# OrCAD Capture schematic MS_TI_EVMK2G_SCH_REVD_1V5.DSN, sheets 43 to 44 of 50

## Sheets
43 42. JTAG_XDS200_CPLD: size C; title: JTAG_XDS200_CPLD
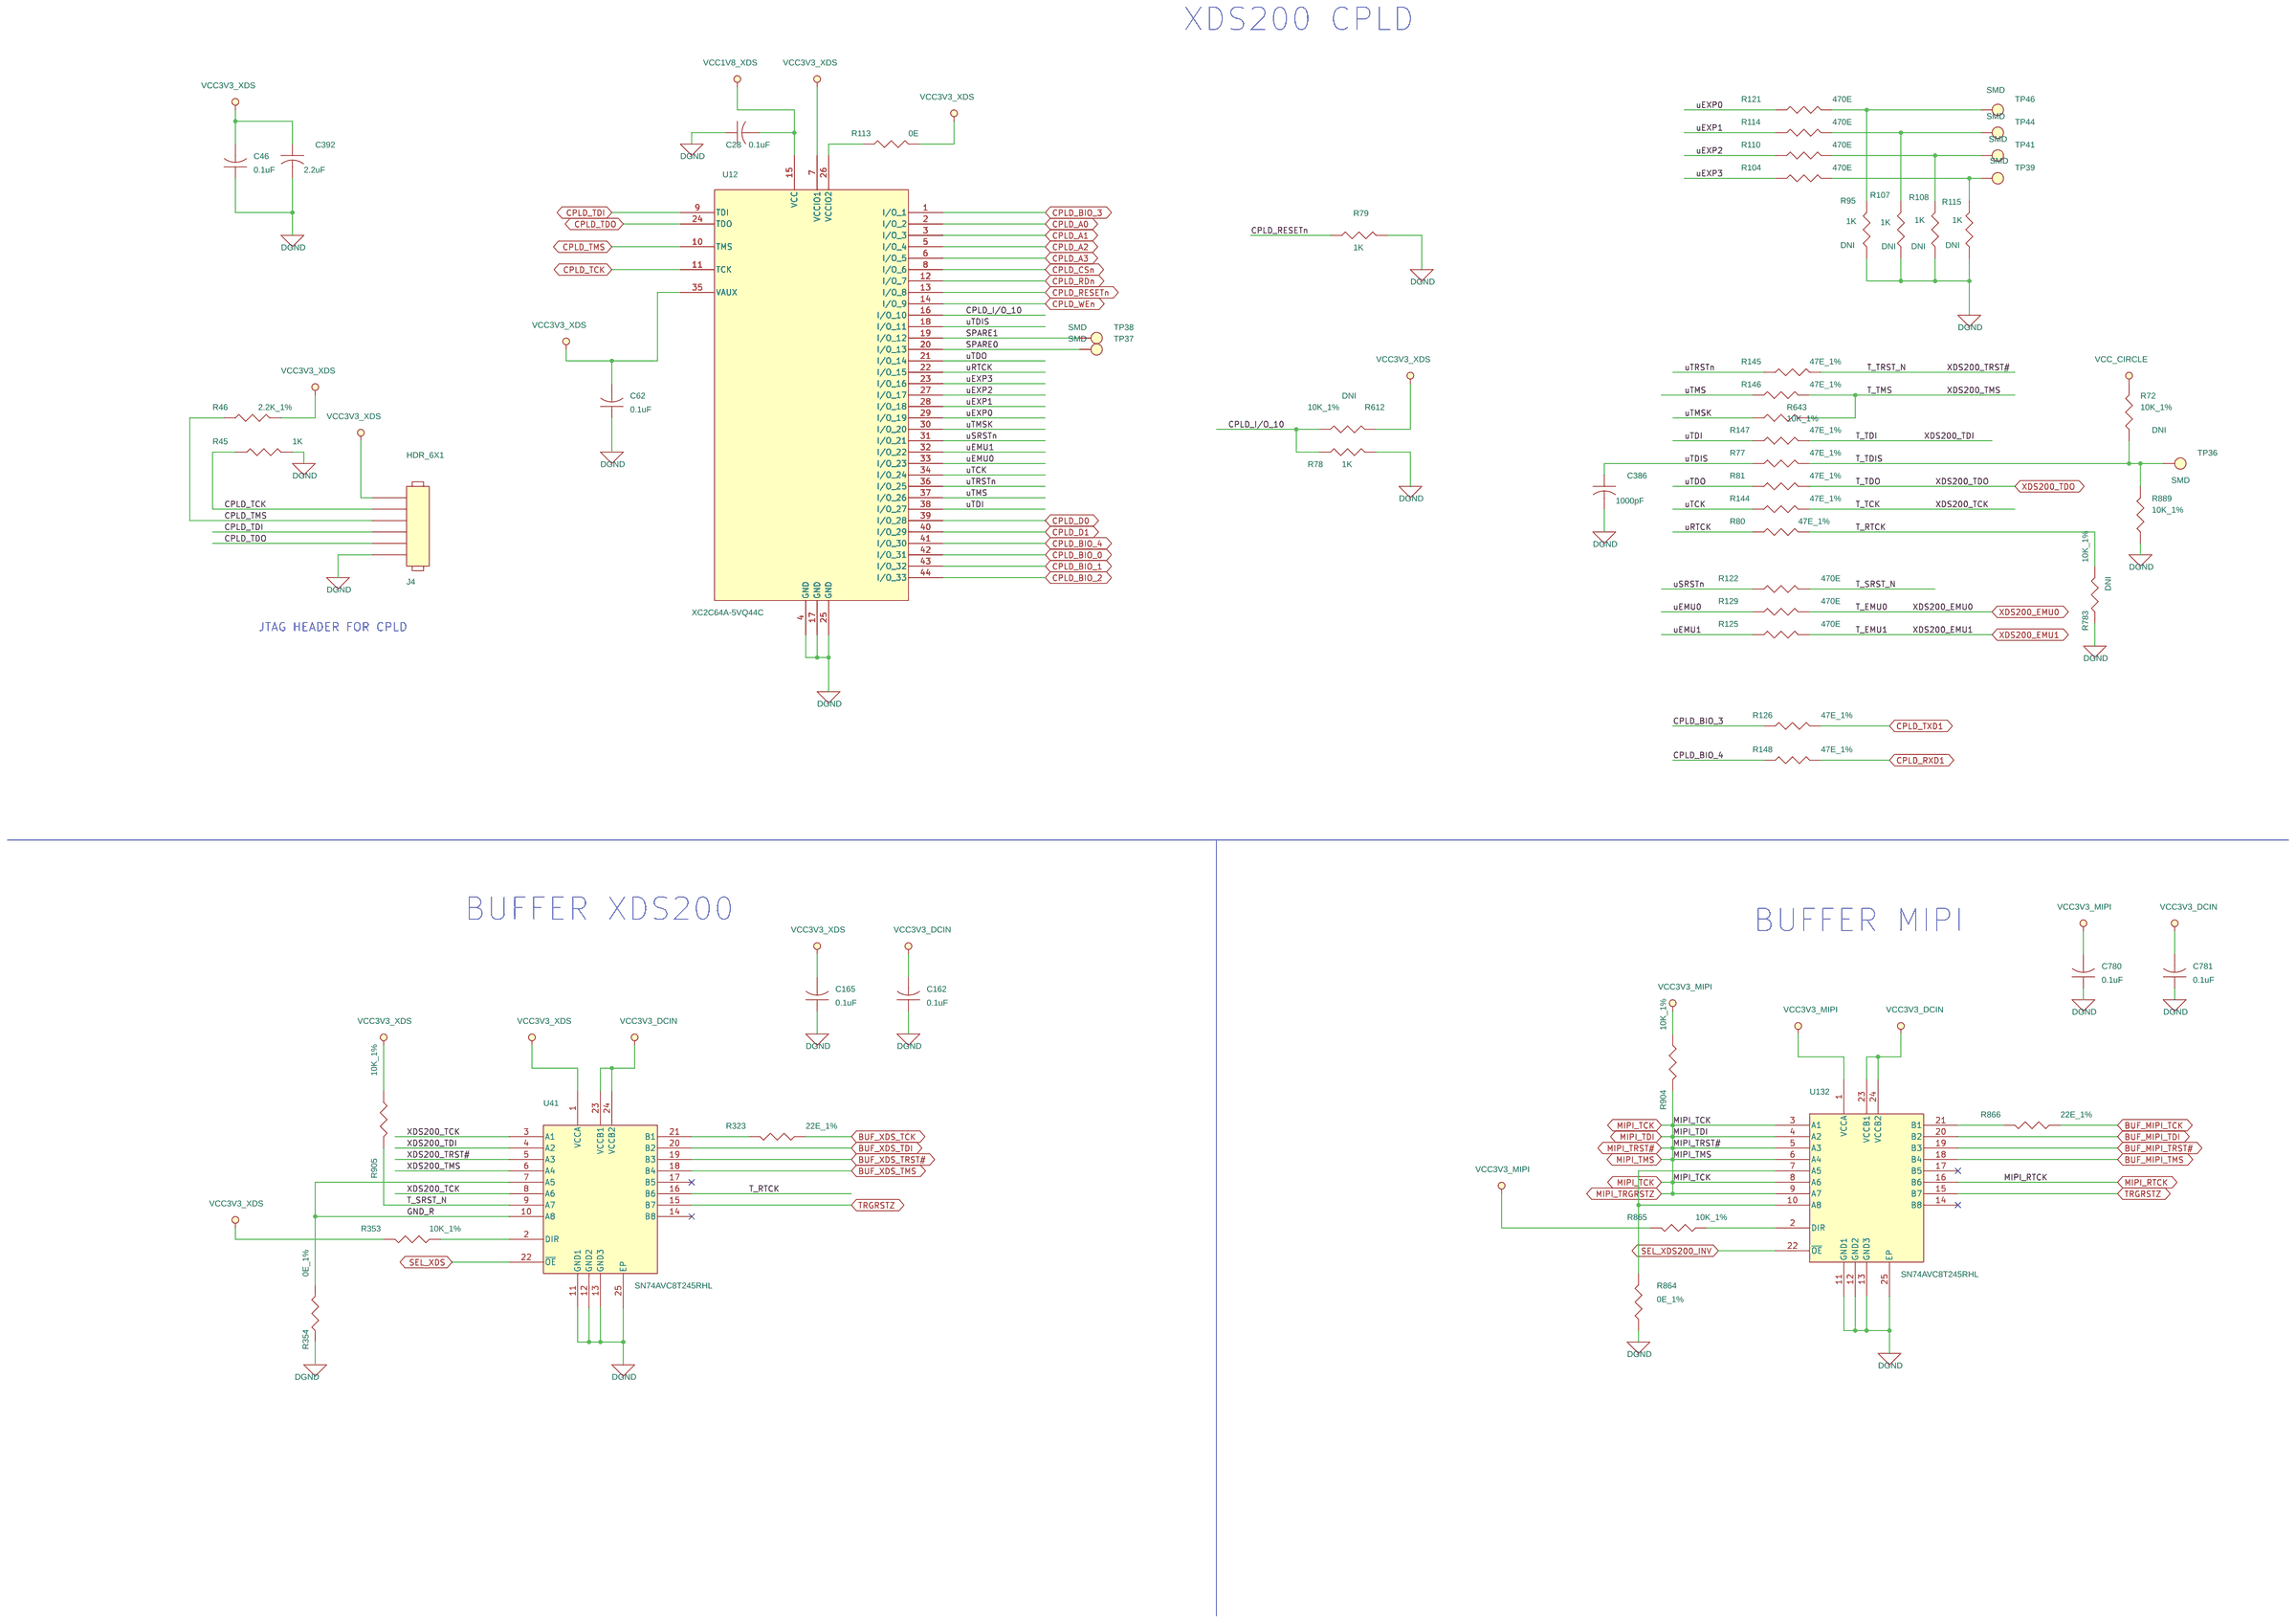
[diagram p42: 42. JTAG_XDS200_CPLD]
44 43. XDS200 POWER: size C; title: XDS200 POWER
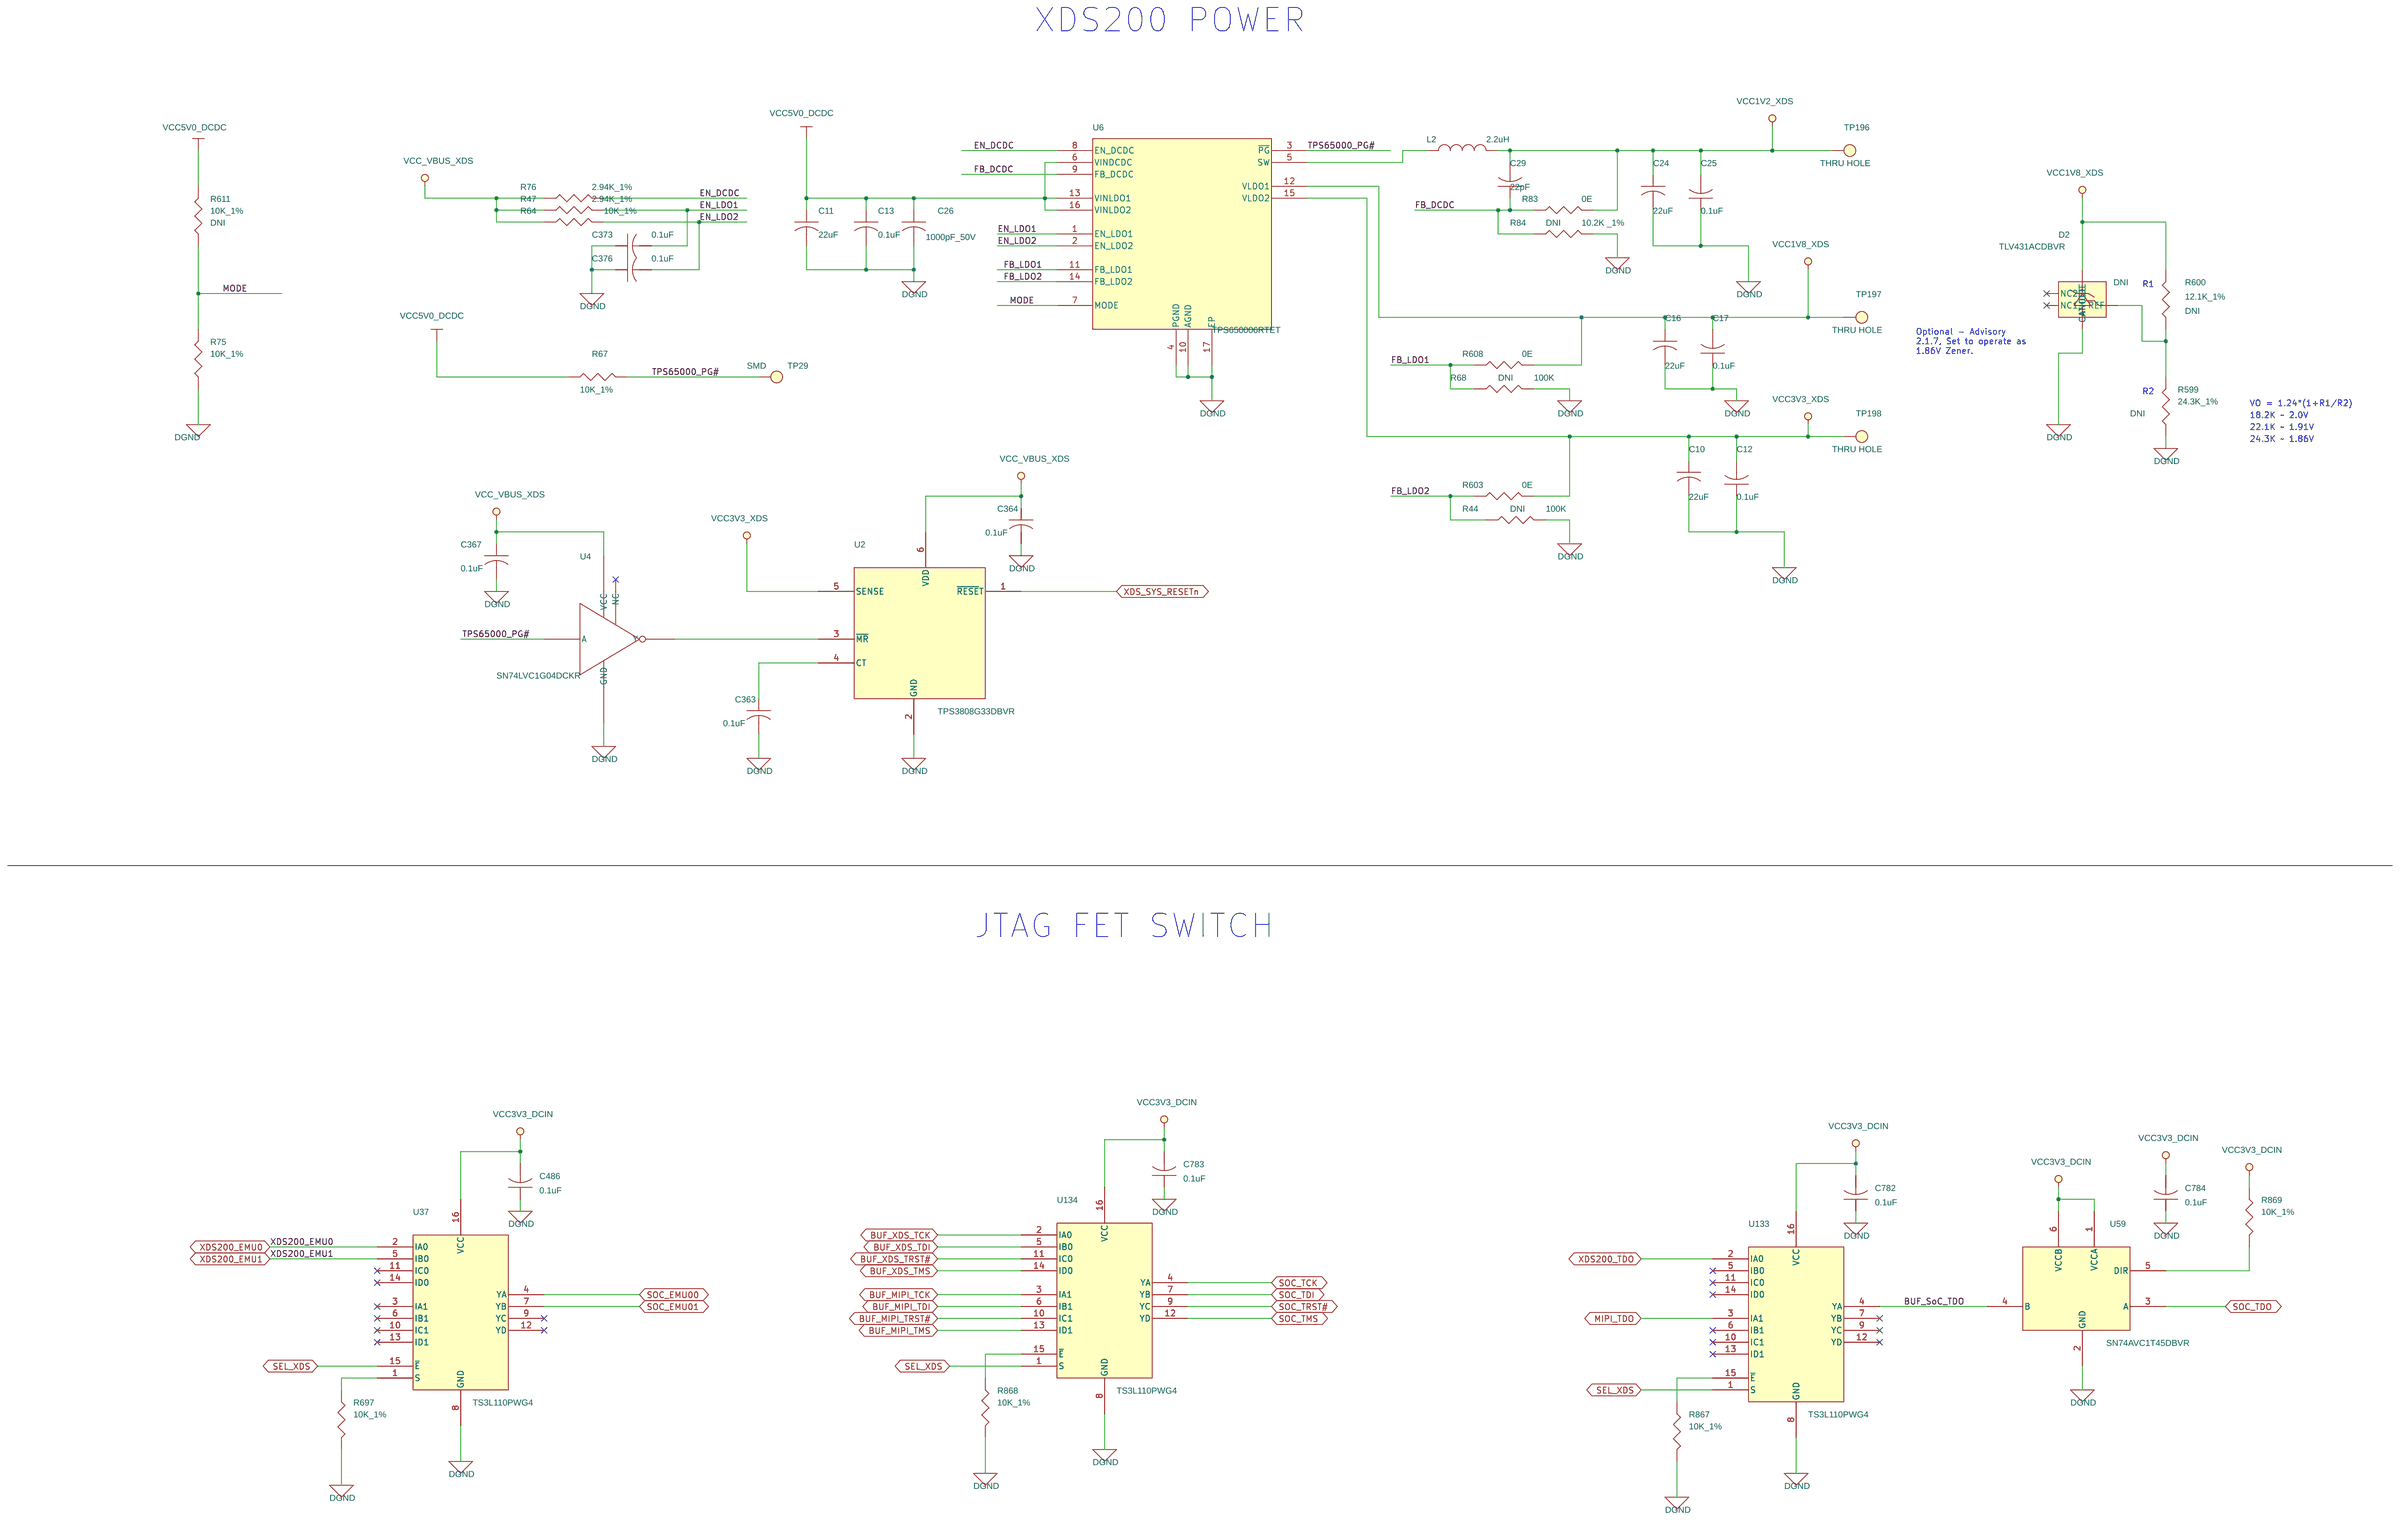
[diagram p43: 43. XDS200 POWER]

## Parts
sheet 42. JTAG_XDS200_CPLD
C28  0.1uF  [CAP0402]
C46  0.1uF  [CAP0402]
C62  0.1uF  [CAP0402]
C162  0.1uF  [CAP0402]
C165  0.1uF  [CAP0402]
C386  1000pF  [CAP0402]
C392  2.2uF  [CAP0402]
C780  0.1uF  [CAP0402]
C781  0.1uF  [CAP0402]
J4  HDR_6X1  [HDR_6X1_100_S_T]
R45  1K  [RES0402]
R46  2.2K_1%  [RES0402]
R72  10K_1%  [RES0402]
R77  47E_1%  [RES0402]
R78  1K  [RES0402]
R79  1K  [RES0402]
R80  47E_1%  [RES0402]
R81  47E_1%  [RES0402]
R95  1K  [RES0402]
R104  470E  [RES0402]
R107  1K  [RES0402]
R108  1K  [RES0402]
R110  470E  [RES0402]
R113  0E  [RES0402]
R114  470E  [RES0402]
R115  1K  [RES0402]
R121  470E  [RES0402]
R122  470E  [RES0402]
R125  470E  [RES0402]
R126  47E_1%  [RES0402]
R129  470E  [RES0402]
R144  47E_1%  [RES0402]
R145  47E_1%  [RES0402]
R146  47E_1%  [RES0402]
R147  47E_1%  [RES0402]
R148  47E_1%  [RES0402]
R323  22E_1%  [RES0402]
R353  10K_1%  [RES0402]
R354  0E_1%  [RES0402]
R612  10K_1%  [RES0402]
R643  10K_1%  [RES0402]
R783  10K_1%  [RES0402]
R864  0E_1%  [RES0402]
R865  10K_1%  [RES0402]
R866  22E_1%  [RES0402]
R889  10K_1%  [RES0402]
R904  10K_1%  [RES0402]
R905  10K_1%  [RES0402]
TP36  SMD  [TP40_SMD]
TP37  SMD  [TP40_SMD]
TP38  SMD  [TP40_SMD]
TP39  SMD  [TP40_SMD]
TP41  SMD  [TP40_SMD]
TP44  SMD  [TP40_SMD]
TP46  SMD  [TP40_SMD]
U12  XC2C64A-5VQ44C  [TQFP44_31-49_400X400]
U41  SN74AVC8T245RHL  [QFN24_19-68_225X145]
U132  SN74AVC8T245RHL  [QFN24_19-68_225X145]
sheet 43. XDS200 POWER
C10  22uF  [CAP0805]
C11  22uF  [CAP0805]
C12  0.1uF  [CAP0402]
C13  0.1uF  [CAP0402]
C16  22uF  [CAP0805]
C17  0.1uF  [CAP0402]
C24  22uF  [CAP0805]
C25  0.1uF  [CAP0402]
C26  1000pF_50V  [CAP0402]
C29  22pF  [CAP0402]
C363  0.1uF  [CAP0402]
C364  0.1uF  [CAP0402]
C367  0.1uF  [CAP0402]
C373  0.1uF  [CAP0402]
C376  0.1uF  [CAP0402]
C486  0.1uF  [CAP0402]
C782  0.1uF  [CAP0402]
C783  0.1uF  [CAP0402]
C784  0.1uF  [CAP0402]
D2  TLV431ACDBVR  [SOT23-5]
L2  2.2uH  [IND1008]
R44  100K  [RES0402]
R47  2.94K_1%  [RES0402]
R64  10K_1%  [RES0402]
R67  10K_1%  [RES0402]
R68  100K  [RES0402]
R75  10K_1%  [RES0402]
R76  2.94K_1%  [RES0402]
R83  0E  [RES0402]
R84  10.2K _1%  [RES0603]
R599  24.3K_1%  [RES0402]
R600  12.1K_1%  [RES0603]
R603  0E  [RES0402]
R608  0E  [RES0402]
R611  10K_1%  [RES0402]
R697  10K_1%  [RES0402]
R867  10K_1%  [RES0402]
R868  10K_1%  [RES0402]
R869  10K_1%  [RES0402]
TP29  SMD  [TP40_SMD]
TP196  THRU HOLE  [TP_40X65]
TP197  THRU HOLE  [TP_40X65]
TP198  THRU HOLE  [TP_40X65]
U2  TPS3808G33DBVR  [SOT23-6]
U4  SN74LVC1G04DCKR  [SC70-5]
U6  TPS650006RTET  [QFN16_19-68_120X120]
U37  TS3L110PWG4  [TSSOP16_25-59_205X180]
U59  SN74AVC1T45DBVR  [SOT23-6]
U133  TS3L110PWG4  [TSSOP16_25-59_205X180]
U134  TS3L110PWG4  [TSSOP16_25-59_205X180]

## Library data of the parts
C12 C13 C17 C25 C28 C46 C62 C162 C165 C363 C364 C367 C373 C376 C486 C780-C784 = CAP: CAP CERAMIC 0.1uF 16V 10% X7R 0402; Alternate_mfr_name_A: KEMET; Alternate_mfr_part_number_A: C0402C104K4RACT; Chkd/date: MAZHAR/281108; Crtd /date: MAZHAR/030907; Custom_Duty: 15%; Customs_HS_Code: 85322990; Distributor_name: DIGIKEY; Distributor_name_A: DIGIKEY; Distributor_part_number: 490-3261-1-ND; Distributor_part_number_A: 399-3521-1-ND; Height: 0.55MM; Mfr_name: MURATA; Mfr_part_number: GRM155R71C104KA88D; Mistral Part No: 120009030060-R; Package: 0402; Part_type: CAPACITORS\CERAMIC; Project: SMART VIEW_IP CAMERA; Tolerance: 10%; Voltage: 16V; Datasheet: Y:\MIS_DATABASE\DATASHEETS\CAPACITORS\GRM188SERIES.PDF
C386 = CAP: CAP CERAMIC 1000pF 50V 5% NP0 0402; Chkd/date: SHREESHAIL/290507; Crtd /date: MAZHAR/290806; Custom_Duty: 15%; Customs_HS_Code: 85322990; Distributor_name: DIGIKEY; Distributor_part_number: 490-3244-1-ND; Height: 0.55MM; Mfr_name: MURATA; Mfr_part_number: GRM1555C1H102JA01D; Mistral Part No: 120009030146; Package: 0402; Part_type: CAPACITORS\CERAMIC; Project: SVDO_RMB_MMA; Tolerance: 5%; Voltage: 50V; Datasheet: Y:\MIS_DATABASE\DATASHEETS\CAPACITORS\GRM188SERIES.PDF
C392 = CAP: CAP CERAMIC 2.2uF 16V 10% X5R 0402; Chkd/date: JAGADISH/280314; Crtd /date: SARANYA/270314; Custom_Duty: 15%; Customs_HS_Code: 85322990; Distributor_name: DIGIKEY; Distributor_part_number: 445-9085-1-ND; Height: 0.55MM; Mfr_name: TDK CORPORATION; Mfr_part_number: C1005X5R1C225K050BC; Mistral Part No: 120014030032-R; Package: 0402; Part_type: CAPACITORS\CERAMIC; Project: DMP; RoHS: RoHS; Temperature: -55°C+85°C; Tolerance: 10%; Voltage: 16V; Wattage: NA; Weight: NA; Datasheet: Y:\MIS_DATABASE\DATASHEETS\CAPACITORS\TDK_CAP.PDF
J4 = HEADER_6X1: CON HDR 6X1 2.54MM PITCH ST TH; Chkd/date: MAZHAR/100311; Crtd /date: BAVISH/210111; Custom_Duty: 24%; Customs_HS_Code: 85369090; Distributor_name: DIGIKEY; Distributor_part_number: A26551-ND; Height: 10.79MM; Mfr_name: TYCO ELECTRONICS; Mfr_part_number: 87224-6; Mistral Part No: 150011010025-R; Package: THRU-HOLE; Part_type: CONNECTOR\HEADERS; Project: OMAPL1_PEC20; RoHS: RoHS; Temperature: NA; Tolerance: NA; Voltage: NA; Wattage: NA; Weight: NA; Datasheet: Y:\MIS_DATABASE\DATASHEETS\CONNECTORS\87224-6.PDF
R45 R78 R79 = RESISTOR: RES 1K 1/16W 5% 0402; Alternate_mfr_name_A: AVX CORPORATION; Alternate_mfr_name_C: YAGEO AMERICA; Alternate_mfr_part_number_A: CR05-102J-H; Alternate_mfr_part_number_C: RC0402JR-071KL; Chkd/date: SHREESHAIL/121205; Crtd /date: MAZHAR/230805; Custom_Duty: 15%; Customs_HS_Code: 85332119; Distributor_name: DIGIKEY; Distributor_name_A: NA; Distributor_name_C: DIGIKEY; Distributor_part_number: P1.0KJCT-ND; Distributor_part_number_A: NA; Distributor_part_number_C: 311-1.0KJRCT-ND; Height: 0.40MM; Mfr_name: PANASONIC-ECG; Mfr_part_number: ERJ-2GEJ102X; Mistral Part No: 110009030400-R; Package: 0402; Part_type: RESISTORS\FIXED; Project: HSE; RoHS: RoHS; Tolerance: 5%; Wattage: 1/16W; Datasheet: Y:\MIS_DATABASE\DATASHEETS\RESISTORS\ERJ12.PDF
R46 = RESISTOR: RES 2.2K 1/16W 1% 0402; Chkd/date: NAVEED/241114; Crtd /date: VASANTHA/101114; Custom_Duty: 15%; Customs_HS_Code: 85332119; Distributor_name: DIGIKEY; Distributor_part_number: 311-2.20KLRCT-ND; Height: 0.40MM; Mfr_name: YAGEO AMERICA; Mfr_part_number: RC0402FR-072K2L; Mistral Part No: 110014110004-R; Package: 0402; Part_type: RESISTORS\FIXED; Project: GALILEO_EVM; RoHS: RoHS; Temperature: -55°C+155°C; Tolerance: 1%; Voltage: NA; Wattage: 1/16W; Weight: NA; Datasheet: Y:\MIS_DATABASE\DATASHEETS\RESISTORS\RC0402FR.PDF
R72 R611 R612 R783 = RESISTOR: RES 10K 1/16W 1% 0402; Alternate_mfr_name_A: AVX CORPORATION; Alternate_mfr_name_B: PANASONIC-ECG-ECG; Alternate_mfr_name_C: YAGEO AMERICA; Alternate_mfr_name_D: VISHAY; Alternate_mfr_part_number_A: CR05-103F-H; Alternate_mfr_part_number_B: ERJ-2RKF1002X; Alternate_mfr_part_number_C: 9C04021A1002FLHF3; Alternate_mfr_part_number_D: CRCW040210K0FKED; Chkd/date: SHREESHAIL/310506; Crtd /date: GEETHA/290506; Custom_Duty: 15%; Customs_HS_Code: 85332119; Distributor_name: DIGIKEY; Distributor_name_A: NA; Distributor_name_B: DIGIKEY; Distributor_name_C: DIGIKEY; Distributor_name_D: DIGIKEY; Distributor_part_number: 311-10.0KLRTR-ND; Distributor_part_number_A: NA; Distributor_part_number_B: P10.0KLCT-ND; Distributor_part_number_C: 311-10.0KLCT-ND; Distributor_part_number_D: 541-10.0KLCT-ND; Height: 0.40MM; Loading: DNI; Mfr_name: YAGEO AMERICA; Mfr_part_number: RC0402FR-0710KL; Mistral Part No: 110009030220-P; Package: 0402; Part_type: RESISTORS\FIXED; Project: VOCERA; RoHS: Pb-Free; Tolerance: 1%; Wattage: 1/16W; Datasheet: Y:\MIS_DATABASE\DATASHEETS\RESISTORS\YAGEO-RC0402.PDF
R77 R80 R81 R126 R144-R148 = RESISTOR: RES 47E 1/16W 1% 0402; Chkd/date: VASANTHA/190614; Crtd /date: NAVEED/160614; Custom_Duty: 15%; Customs_HS_Code: 85332119; Distributor_name: DIGIKEY; Distributor_part_number: RMCF0402FT47R0CT-ND; Height: 0.40MM; Mfr_name: STACKPOLE ELECTRONICS; Mfr_part_number: RMCF0402FT47R0; Mistral Part No: 110014060027-R; Package: 0402; Part_type: RESISTORS\FIXED; Project: AEGIS_POM; RoHS: RoHS; Temperature: -55°C+155°C; Tolerance: 1%; Voltage: NA; Wattage: 1/16W; Weight: NA; Datasheet: Y:\MIS_DATABASE\DATASHEETS\RESISTORS\RMCF-SERIES1.PDF
R95 R107 R108 R115 = RESISTOR: RES 1K 1/16W 5% 0402; Alternate_mfr_name_A: AVX CORPORATION; Alternate_mfr_name_C: YAGEO AMERICA; Alternate_mfr_part_number_A: CR05-102J-H; Alternate_mfr_part_number_C: RC0402JR-071KL; Chkd/date: SHREESHAIL/121205; Crtd /date: MAZHAR/230805; Custom_Duty: 15%; Customs_HS_Code: 85332119; Distributor_name: DIGIKEY; Distributor_name_A: NA; Distributor_name_C: DIGIKEY; Distributor_part_number: P1.0KJCT-ND; Distributor_part_number_A: NA; Distributor_part_number_C: 311-1.0KJRCT-ND; Height: 0.40MM; Loading: DNI; Mfr_name: PANASONIC-ECG; Mfr_part_number: ERJ-2GEJ102X; Mistral Part No: 110009030400-R; Package: 0402; Part_type: RESISTORS\FIXED; Project: HSE; RoHS: RoHS; Tolerance: 5%; Wattage: 1/16W; Datasheet: Y:\MIS_DATABASE\DATASHEETS\RESISTORS\ERJ12.PDF
R104 R110 R114 R121 R122 R125 R129 = RESISTOR: RES 470E 1/16W 5% 0402; Alternate_mfr_name_A: AVX CORPORATION; Alternate_mfr_name_C: YAGEO AMERICA; Alternate_mfr_part_number_A: CR05-471J-H; Alternate_mfr_part_number_C: 9C04021A4700JLHF3; Chkd/date: SHREESHAIL/24050; Crtd /date: MAZHAR/260706; Custom_Duty: 15%; Customs_HS_Code: 85332119; Distributor_name: DIGIKEY; Distributor_name_A: NA; Distributor_name_C: DIGIKEY; Distributor_part_number: P470JCT-ND; Distributor_part_number_A: NA; Distributor_part_number_C: 311-470JCT-ND; Height: 0.40MM; Mfr_name: PANASONIC-ECG; Mfr_part_number: ERJ-2GEJ471X; Mistral Part No: 110009030859-R; Package: 0402; Part_type: RESISTORS\FIXED; Project: POWERBOX; RoHS: RoHS; Tolerance: 5%; Wattage: 1/16W; Datasheet: Y:\MIS_DATABASE\DATASHEETS\RESISTORS\ERJ12.PDF
R83 R113 R603 R608 = RESISTOR: RES 0E 1/10W 5% 0402; Chkd/date: NAVEED/241114; Crtd /date: NAVEED/201014; Custom_Duty: 15%; Customs_HS_Code: 85332119; Distributor_name: DIGIKEY; Distributor_part_number: P0.0JCT-ND; Height: 0.40MM; Mfr_name: PANASONIC-ECG; Mfr_part_number: ERJ-2GE0R00X; Mistral Part No: 110014100008-R; Package: 0402; Part_type: RESISTORS\FIXED; Project: AEGIS POM; RoHS: RoHS; Tolerance: 5%; Wattage: 1/10W; Datasheet: Y:\MIS_DATABASE\DATASHEETS\RESISTORS\ERJ12.PDF
R323 R866 = RESISTOR: RES 22E 1/16W 1% 0402; Alternate_mfr_name_A: VISHAY; Alternate_mfr_part_number_A: CRCW040222R0FKED; Chkd/date: SUHAS/290910; Crtd /date: MAZHAR/090909; Custom_Duty: 15%; Customs_HS_Code: 85332119; Distributor_name: DIGIKEY; Distributor_name_A: DIGIKEY; Distributor_part_number: 311-22.0LRCT-ND; Distributor_part_number_A: 541-22.0LCT-ND; Height: 0.40MM; Mfr_name: YAGEO AMERICA; Mfr_part_number: RC0402FR-0722RL; Mistral Part No: 110009090004-P; Package: 0402; Part_type: RESISTORS\FIXED; Project: VMEFMCD; Remarks: In alternate datasheet it is RoHS COMPLIANT. Y:\MIS_DATABASE\DATASHEETS\RESISTORS\CRCW0402.PDF; RoHS: Pb-Free; Temperature: -55°C+155°C; Tolerance: 1%; Voltage: 50V; Wattage: 1/16W; Weight: 0.8g/1000pcs; Datasheet: Y:\MIS_DATABASE\DATASHEETS\RESISTORS\YAGEO-RC0402.PDF
R64 R67 R75 R353 R643 R697 R865 R867-R869 R889 R904 R905 = RESISTOR: RES 10K 1/16W 1% 0402; Alternate_mfr_name_A: AVX CORPORATION; Alternate_mfr_name_B: PANASONIC-ECG-ECG; Alternate_mfr_name_C: YAGEO AMERICA; Alternate_mfr_name_D: VISHAY; Alternate_mfr_part_number_A: CR05-103F-H; Alternate_mfr_part_number_B: ERJ-2RKF1002X; Alternate_mfr_part_number_C: 9C04021A1002FLHF3; Alternate_mfr_part_number_D: CRCW040210K0FKED; Chkd/date: SHREESHAIL/310506; Crtd /date: GEETHA/290506; Custom_Duty: 15%; Customs_HS_Code: 85332119; Distributor_name: DIGIKEY; Distributor_name_A: NA; Distributor_name_B: DIGIKEY; Distributor_name_C: DIGIKEY; Distributor_name_D: DIGIKEY; Distributor_part_number: 311-10.0KLRTR-ND; Distributor_part_number_A: NA; Distributor_part_number_B: P10.0KLCT-ND; Distributor_part_number_C: 311-10.0KLCT-ND; Distributor_part_number_D: 541-10.0KLCT-ND; Height: 0.40MM; Mfr_name: YAGEO AMERICA; Mfr_part_number: RC0402FR-0710KL; Mistral Part No: 110009030220-P; Package: 0402; Part_type: RESISTORS\FIXED; Project: VOCERA; RoHS: Pb-Free; Tolerance: 1%; Wattage: 1/16W; Datasheet: Y:\MIS_DATABASE\DATASHEETS\RESISTORS\YAGEO-RC0402.PDF
R354 R864 = RESISTOR: RES 0E 1/16W 1% 0402; Chkd/date: MAZHAR/220709; Crtd /date: USMAN/270109; Custom_Duty: 15%; Customs_HS_Code: 85332119; Distributor_name: NA; Distributor_part_number: NA; Height: 0.40MM; Mfr_name: YAGEO AMERICA; Mfr_part_number: RC0402FR-070RL; Mistral Part No: 110009030085-P; Package: 0402; Part_type: RESISTORS\FIXED; Project: OMAP_EVM; RoHS: Pb-Free; Tolerance: 1%; Wattage: 1/16W; Datasheet: Y:\MIS_DATABASE\DATASHEETS\RESISTORS\CRCW0603.PDF
TP29 TP36-TP39 TP41 TP44 TP46 = TESTPOINT: TESTPOINT 40 SMD; Chkd/date: MAZHAR/190505; Crtd /date: MAZHAR/190505; Distributor_name: NA; Distributor_part_number: NA; Height: NA; Mfr_name: LOCAL; Mistral Part No: 130009030933; Part_type: MISC\TESTPOINT; Project: RAINIER-3
U12 = XC2C64A-5VQ44C_TQFP44: IC COOLRUNNER-II CPLD TQFP44; Chkd/date: NAVEED/060115; Crtd /date: VASANTHA/111014; Custom_Duty: 15%; Customs_HS_Code: 85423100; Distributor_name: DIGIKEY; Distributor_part_number: XC2C64A-5VQ44C-ND; Height: 1.20MM; Mfr_name: XILINX; Mistral Part No: 141014100011; Package: TQFP44; Part_type: ICS\DIGITAL\PLD; Project: GALILEO_EVM; Temperature: -0°C+70°C; Tolerance: NA; Voltage: NA; Wattage: NA; Weight: NA; Datasheet: Y:\MIS_DATABASE\DATASHEETS\ICS\DIGITAL\PLD\XC2C64A.PDF
U41 U132 = SN74AVC8T245RHL_QFN24: IC BUS TRANSCEIVER 8-BIT DUAL-SUPPLY QFN24; Chkd/date: RAGESH/050511; Crtd /date: BAVISH/290411; Custom_Duty: 15%; Customs_HS_Code: 85423100; Distributor_name: DIGIKEY; Distributor_part_number: 296-17859-1-ND; Height: 1.20MM; Mfr_name: TEXAS INSTRUMENTS; Mfr_part_number: SN74AVC8T245RHLR; Mistral Part No: 143011040001-R; Package: QFN24; Part_type: ICS\TELECOM\TRANSCEIVER; Project: OMAPL1_PEC20; RoHS: RoHS; Temperature: -40°C+85°C; Tolerance: NA; Voltage: NA; Wattage: NA; Weight: NA; Datasheet: Y:\MIS_DATABASE\DATASHEETS\ICS\DIGITAL\BUSTRANSCEIVER\SN74AVC8T245.PDF
C10 C11 C16 C24 = CAP: CAP CERAMIC 22uF 16V 10% X5R 0805; Chkd/date: MAZHAR/291110; Crtd /date: BAVISH/271110; Custom_Duty: 15%; Customs_HS_Code: 85322990; Distributor_name: NA; Distributor_part_number: NA; Height: 1.45MM; Mfr_name: TDK CORPORATION; Mfr_part_number: C2012X5R1C226K; Mistral Part No: 120010110025-R; Package: 0805; Part_type: CAPACITORS\CERAMIC; Project: EM-FLS; RoHS: RoHS; Temperature: -55°C+85°C; Tolerance: 10%; Voltage: 16V; Wattage: NA; Weight: NA; Datasheet: Y:\MIS_DATABASE\DATASHEETS\CAPACITORS\C2012.PDF
C26 = CAP: CAP CERAMIC 1000pF 50V 10% X7R 0402; Alternate_mfr_name_A: MURATA; Alternate_mfr_name_B: YAGEO; Alternate_mfr_name_D: YAGEO AMERICA; Alternate_mfr_part_number_A: GRM155R71H102KA01D; Alternate_mfr_part_number_B: CC0402KRX7R9BB102; Alternate_mfr_part_number_D: 04022R102K9B20D; Chkd/date: SHREESHAIL/280507; Crtd /date: MAZHAR/250706; Custom_Duty: 15%; Customs_HS_Code: 85322990; Distributor_name: NA; Distributor_name_A: DIGIKEY; Distributor_name_B: DIGIKEY; Distributor_name_D: DIGIKEY; Distributor_part_number: NA; Distributor_part_number_A: 490-1303-1-ND; Distributor_part_number_B: 311-1036-1-ND; Distributor_part_number_D: 311-1036-1-ND; Height: 0.63MM; Mfr_name: VENKEL; Mfr_part_number: C0402X7R500-102KNE; Mistral Part No: 120009030154-R; Package: 0402; Part_type: CAPACITORS\CERAMIC; Project: POWERBOX; RoHS: RoHS; Temperature: -55°C+125°C; Tolerance: 10%; Voltage: 50V; Wattage: NA; Weight: NA; Datasheet: Y:\MIS_DATABASE\DATASHEETS\CAPACITORS\C0402.PDF
C29 = CAP: CAP CERAMIC 22pF 25V 5% NP0 0402; Chkd/date: SHREESHAIL/291105; Crtd /date: MAZHAR/040505; Custom_Duty: 15%; Customs_HS_Code: 85322990; Distributor_name: DIGIKEY; Distributor_part_number: 04023A220JAT2A-ND; Height: 0.60MM; Mfr_name: AVX CORPORATION; Mfr_part_number: 04023A220JAT2A; Mistral Part No: 120009030322-R; Package: 0402; Part_type: CAPACITORS\CERAMIC; Project: TELEMATICS-02; RoHS: RoHS; Tolerance: 5%; Voltage: 25V; Datasheet: Y:\MIS_DATABASE\DATASHEETS\CAPACITORS\AVX_MLC.PDF
D2 = TLV431AQDBVR_SOT23-5: IC LOW VOLTAGE ADJUSTABLE PRECISION SHUNT REGULATORS SOT23-5; Chkd/date: NAVEED/241114; Crtd /date: VASANTHA/281014; Custom_Duty: 15%; Customs_HS_Code: 85423100; Distributor_name: DIGIKEY; Distributor_part_number: 296-1348-1-ND; Height: 1.45MM; Loading: DNI; Mfr_name: TEXAS INSTRUMENTS; Mistral Part No: 142014100024-R; Part_type: ICS\POWER\VOLTAGE REGULATOR; Project: GALILEO_EVM; RoHS: RoHS; Temperature: -0°C+70°C; Tolerance: NA; Voltage: NA; Wattage: NA; Weight: NA; Datasheet: Y:\MIS_DATABASE\DATASHEETS\MISC\REGULATORS\TLV431.PDF
L2 = INDUCTOR: IND CHIP COIL 2.2uH 20% 1008; Chkd/date: NAVEED/241114; Crtd /date: USMAN/170613; Custom_Duty: 24%; Customs_HS_Code: 85369090; Distributor_name: DIGIKEY; Distributor_part_number: 490-6700-1-ND; Height: 1.20MM; Mfr_name: MURATA; Mfr_part_number: LQM2HPN2R2MJ0; Mistral Part No: 130013060021-R; Package: 1008; Project: GEN_3-8; RoHS: RoHS; Temperature: -55°C+125°C; Tolerance: 20%; Voltage: NA; Wattage: NA; Weight: NA; Datasheet: Y:\MIS_DATABASE\DATASHEETS\DISCRETES\INDUCTORS\LQM2HPN.PDF
R44 R68 = RESISTOR: RES 100K 1/16W 5% 0402; Assembly instruction: DNI; Chkd/date: JAGADEESWARAN.S/250414; Crtd /date: BAVISH/010611; Custom_Duty: 15%; Customs_HS_Code: 85332119; Distributor_name: DIGIKEY; Distributor_part_number: 541-100KJCT-ND; Height: 0.40MM; Loading: DNI; Mfr_name: VISHAY; Mfr_part_number: CRCW0402100KJNED; Mistral Part No: 110011060002-R; Package: 0402; Part_type: RESISTORS\FIXED; Project: AM4515_EVM_LCD; RoHS: RoHS; Temperature: -55°C+155°C; Tolerance: 5%; Voltage: NA; Wattage: 1/16W; Weight: 0.65mg; Datasheet: Y:\MIS_DATABASE\DATASHEETS\RESISTORS\CRCW0603.PDF
R47 R76 = RESISTOR: RES 2.94K 1/16W 1% 0402; Alternate_mfr_name_A: VISHAY; Alternate_mfr_name_B: PANASONIC-ECG; Alternate_mfr_part_number_A: CRCW04022K94FKED; Alternate_mfr_part_number_B: ERJ-2RKF2941X; Chkd/date: SHREESHAIL/100807; Crtd /date: MAZHAR/090807; Custom_Duty: 15%; Customs_HS_Code: 85332119; Distributor_name: NA; Distributor_name_A: DIGIKEY; Distributor_name_B: DIGIKEY; Distributor_part_number: NA; Distributor_part_number_A: 541-2.94KLCT-ND; Distributor_part_number_B: P2.94KLCT-ND; Height: 0.40MM; Mfr_name: PANASONIC-ECG; Mfr_part_number: ERJ-2RNF2941V; Mistral Part No: 110009030460-R; Package: 0402; Part_type: RESISTORS\FIXED; Project: TELEMETRY ENCODER; RoHS: RoHS; Tolerance: 1%; Wattage: 1/16W; Datasheet: Y:\MIS_DATABASE\DATASHEETS\RESISTORS\PAN_ERJ.PDF
R84 = RESISTOR: RES 10.2K 1/10W 1% 0603; Assembly instruction: DNI; Chkd/date: MAZHAR/220709; Crtd /date: MAZHAR/120907; Custom_Duty: 15%; Customs_HS_Code: 85332119; Distributor_name: DIGIKEY; Distributor_part_number: 311-10.2KHRCT-ND; Height: 0.55MM; Loading: DNI; Mfr_name: YAGEO AMERICA; Mfr_part_number: RC0603FR-0710K2L; Mistral Part No: 110009030152-P; Package: 0603; Part_type: RESISTORS\FIXED; Project: SMART VIEW_IP CAMERA; RoHS: Pb-Free; Tolerance: 1%; Wattage: 1/10W; Datasheet: Y:\MIS_DATABASE\DATASHEETS\RESISTORS\RC0603.PDF
R599 = RESISTOR: RES 24.3K 1/16W 1% 0402; Chkd/date: MAZHAR/220408; Crtd /date: USMAN/170408; Custom_Duty: 15%; Customs_HS_Code: 85332119; Distributor_name: DIGIKEY; Distributor_part_number: 541-24.3KLCT-ND; Height: 0.40MM; Loading: DNI; Mfr_name: VISHAY; Mfr_part_number: CRCW040224K3FKED; Mistral Part No: 110009030535-P; Package: 0402; Part_type: RESISTORS\FIXED; Project: MDTV; RoHS: Pb-Free; Tolerance: 1%; Wattage: 1/16W; Datasheet: Y:\MIS_DATABASE\DATASHEETS\RESISTORS\CRCW0603.PDF
R600 = RESISTOR: RES 12.1K 1/10W 1% 0603; Alternate_mfr_name_A: YAGEO AMERICA; Alternate_mfr_name_D: VISHAY; Alternate_mfr_part_number_A: RC0603FR-0712K1L; Alternate_mfr_part_number_D: CRCW060312K1FKEA; Chkd/date: MAZHAR/310508; Crtd /date: MAZHAR/170907; Custom_Duty: 15%; Customs_HS_Code: 85332119; Distributor_name: DIGIKEY; Distributor_name_A: DIGIKEY; Distributor_name_D: DIGIKEY; Distributor_part_number: P12.1KHCT-ND; Distributor_part_number_A: 311-12.1KHRCT-ND; Distributor_part_number_D: 541-12.1KHCT-ND; Height: 0.55MM; Loading: DNI; Mfr_name: PANASONIC-ECG; Mfr_part_number: ERJ-3EKF1212V; Mistral Part No: 110009030247-R; Package: 0603; Part_type: RESISTORS\FIXED; Project: SMART VIEW_NVR; RoHS: RoHS; Temperature: -55°C+155°C; Tolerance: 1%; Voltage: NA; Wattage: 1/10W; Weight: 2/1000g; Datasheet: Y:\MIS_DATABASE\DATASHEETS\RESISTORS\PAN_ERJ.PDF
TP196-TP198 = TESTPOINT: TESTPOINT 1.0MM DRILL PTH; Chkd/date: MAZHAR/271211; Crtd /date: SHREESHAIL/041005; Distributor_name: NA; Distributor_part_number: NA; Height: NA; Mfr_name: LOCAL; Mistral Part No: 130009030938; Package: THRU-HOLE; Part_type: MISC\TESTPOINT; Project: HSE; Datasheet: NA
U2 = TPS3808G33DBV_SOT23-6: IC VOLT SUPERVISOR 3.3V SOT23-6; Chkd/date: SUHAS/050411; Crtd /date: MAZHAR/031210; Custom_Duty: 15%; Customs_HS_Code: 85423100; Distributor_name: DIGIKEY; Distributor_part_number: 296-17195-1-ND; Height: 1.45MM; Mfr_name: TEXAS INSTRUMENTS; Mistral Part No: 142010120003-R; Part_type: ICS\POWER\VOLTAGE REGULATOR; Project: IEMS; RoHS: Sb/ Br FREE; Temperature: -40°C+125°C; Weight: NA; Datasheet: Y:\MIS_DATABASE\DATASHEETS\ICS\POWER\TPS3808G33.PDF
U4 = SN74LVC1G04DCKR_SC70-5: IC SINGLE INVERTER GATE SC70-5; Chkd/date: SUHAS/221010; Crtd /date: USMAN/150709; Custom_Duty: 15%; Customs_HS_Code: 85423100; Distributor_name: DIGIKEY; Distributor_part_number: 296-11600-1-ND; Height: 1.10MM; Mfr_name: TEXAS INSTRUMENTS; Mistral Part No: 141009070007-R; Part_type: ICS\DIGITAL\GATES; Project: BUG_BASE-II; RoHS: Sb/ Br FREE; Temperature: -40°C+85°C; Datasheet: Y:\MIS_DATABASE\DATASHEETS\ICS\DIGITAL\GATES\SN74LVC1G04-1.PDF
U6 = TPS650006RTET_QFN16: IC STEP-DOWN CONVERTER WITH DUAL LDO AND SVS WQFN16; Chkd/date: NAVEED/060115; Crtd /date: JEBRAN/101014; Custom_Duty: 15%; Customs_HS_Code: 85423100; Distributor_name: DIGIKEY; Distributor_part_number: 296-25357-1-ND; Height: 0.80MM; Mfr_name: TEXAS INSTRUMENTS; Mistral Part No: 142014100007-R; Package: WQFN16; Part_type: ICS\POWER\MANAGEMENT; Project: GALILEO EVM; RoHS: RoHS; Temperature: -40°C+85°C; Tolerance: NA; Voltage: NA; Wattage: NA; Weight: NA; Datasheet: Y:\MIS_DATABASE\DATASHEETS\ICS\POWER\TPS65001RUK.PDF
U37 U133 U134 = TS3L110PWG4_TSSOP16: IC QUAD SPDT SWITCH 8-4 CHANNEL MULTIPLEXER/DEMULTIPLEXER TSSOP16; Chkd/date: NAVEED/060115; Crtd /date: JEBRAN/051114; Custom_Duty: 15%; Customs_HS_Code: 85369090; Distributor_name: DIGIKEY; Distributor_part_number: TS3L110PWG4-ND; Height: 1.20MM; Mfr_name: TEXAS INSTRUMENTS; Mistral Part No: 140114110002-R; Package: TSSOP16; Part_type: ICS\ANALOG\APPLICATION SPECIFIC; Project: GALILEO EVM; RoHS: RoHS; Temperature: -40°C+85°C; Tolerance: NA; Voltage: NA; Wattage: NA; Weight: NA; Datasheet: Y:\MIS_DATABASE\DATASHEETS\ICS\DIGITAL\COMBINATIONAL\TS3L110_SERIES.PDF
U59 = SN74AVC1T45DBVR_SOT23-6: IC SINGLE-BIT DUAL-SUPPLY BUS TRANSCEIVER SOT23-6; Chkd/date: MAZHAR/050208; Crtd /date: USMAN/050208; Custom_Duty: 15%; Customs_HS_Code: 85423100; Distributor_name: DIGIKEY; Distributor_part_number: 296-19094-1-ND; Height: 1.45MM; Mfr_name: TEXAS INSTRUMENTS; Mistral Part No: 141009030019-R; Part_type: ICS\DIGITAL\BUSTRANSCEIVER; Project: HS100RD; RoHS: RoHS; Datasheet: Y:\MIS_DATABASE\DATASHEETS\ICS\DIGITAL\BUSTRANSCEIVER\SN74AVC1T45.PDF

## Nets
DGND: C10.2 C11.2 C12.1 C13.2 C16.2 C17.1 C24.2 C25.1 C26.2 C28.1 C46.1 C62.1 C162.1 C165.1 C363.2 C364.2 C367.2 C373.1 C376.1 C386.2 C392.2 C486.1 C780.1 C781.1 C782.1 C783.1 C784.1 D2.5(ANODE) J4.6 R44.2 R45.2 R68.2 R75.1 R78.2 R79.2 R84.2 R95.1 R107.1 R108.1 R115.1 R354.1 R599.2 R697.2 R783.1 R864.1 R867.2 R868.2 R889.1 U2.2(GND) U4.3(GND) U6.4(PGND) U6.10(AGND) U6.17(EP) U12.4(GND) U12.17(GND) U12.25(GND) U37.8(GND) U41.11(GND1) U41.12(GND2) U41.13(GND3) U41.25(EP) U59.2(GND) U132.11(GND1) U132.12(GND2) U132.13(GND3) U132.25(EP) U133.8(GND) U134.8(GND) ; also on sheet 1 11 12 13 14 15 16 17 18 19 20 21 22 23 24 25 26 27 28 29 30 31 32 33 34 35 36 37 38 39 40 41 42 45 46 47 48 49 50
GND_R: R354.2 U41.7(A5) U41.10(A8)
VCC1V2_XDS: C24.1 C25.2 C29.2 L2.2 R83.2 TP196.1(TP) ; also on sheet 42
VCC1V8_XDS: C16.1 C17.2 C28.2 D2.3(CATHODE) R600.1 R608.2 TP197.1(TP) U6.12(VLDO1) U12.15(VCC) ; also on sheet 42
VCC3V3_DCIN: C162.2 C486.2 C781.2 C782.2 C783.2 C784.2 R869.1 U37.16(VCC) U41.23(VCCB1) U41.24(VCCB2) U59.1(VCCA) U59.6(VCCB) U132.23(VCCB1) U132.24(VCCB2) U133.16(VCC) U134.16(VCC) ; also on sheet 11 17 18 19 20 21 22 23 24 25 26 27 28 29 30 31 32 33 34 35 36 37 38 45 46 47 48 50
VCC3V3_MIPI: C780.2 R865.2 R904.1 U132.1(VCCA) ; also on sheet 38
VCC3V3_XDS: C10.1 C12.2 C46.2 C62.2 C165.2 C392.1 J4.1 R46.2 R72.2 R113.2 R353.2 R603.2 R612.2 R905.1 TP198.1(TP) U2.5(SENSE) U6.15(VLDO2) U12.7(VCCIO1) U12.35(VAUX) U41.1(VCCA) ; also on sheet 39 40 41 42
VCC5V0_DCDC: C11.1 C13.1 C26.1 R67.2 R611.2 U6.6(VINDCDC) U6.13(VINLDO1) U6.16(VINLDO2) ; also on sheet 21 22 27 30 46 48 49 50
VCC_VBUS_XDS: C364.1 C367.1 R47.1 R64.2 R76.1 U2.6(VDD) U4.5(VCC) ; also on sheet 39
BUF_MIPI_TCK: R866.1 U134.3(IA1)
BUF_MIPI_TDI: U132.20(B2) U134.6(IB1)
BUF_MIPI_TMS: U132.18(B4) U134.13(ID1)
BUF_MIPI_TRST#: U132.19(B3) U134.10(IC1)
BUF_SoC_TDO: U59.4(B) U133.4(YA)
BUF_XDS_TCK: R323.1 U134.2(IA0)
BUF_XDS_TDI: U41.20(B2) U134.5(IB0)
BUF_XDS_TMS: U41.18(B4) U134.14(ID0)
BUF_XDS_TRST#: U41.19(B3) U134.11(IC0)
CPLD_A0: U12.2(I/O) ; also on sheet 40
CPLD_A1: U12.3(I/O) ; also on sheet 40
CPLD_A2: U12.5(I/O_4) ; also on sheet 40
CPLD_A3: U12.6(I/O_5) ; also on sheet 40
CPLD_BIO_0: U12.42(I/O_31) ; also on sheet 40
CPLD_BIO_1: U12.43(I/O_32) ; also on sheet 40
CPLD_BIO_2: U12.44(I/O_33) ; also on sheet 40
CPLD_BIO_3: R126.1 U12.1(I/O) ; also on sheet 40
CPLD_BIO_4: R148.1 U12.41(I/O_30) ; also on sheet 40
CPLD_CSn: U12.8(I/O_6) ; also on sheet 40
CPLD_D0: U12.39(I/O_28) ; also on sheet 40
CPLD_D1: U12.40(I/O_29) ; also on sheet 40
CPLD_I/O_10: R78.1 R612.1 U12.16(I/O_10)
CPLD_RDn: U12.12(I/O_7) ; also on sheet 40
CPLD_RESETn: R79.1 U12.13(I/O_8) ; also on sheet 40
CPLD_RXD1: R148.2 ; also on sheet 39
CPLD_TCK: J4.2 R45.1 U12.11(TCK) ; also on sheet 41
CPLD_TDI: J4.4 U12.9(TDI) ; also on sheet 41
CPLD_TDO: J4.5 U12.24(TDO) ; also on sheet 41
CPLD_TMS: J4.3 R46.1 U12.10(TMS) ; also on sheet 41
CPLD_TXD1: R126.2 ; also on sheet 39
CPLD_WEn: U12.14(I/O_9) ; also on sheet 40
EN_DCDC: R76.2 U6.8(EN_DCDC)
EN_LDO1: C373.2 R47.2 U6.1(EN_LDO1)
EN_LDO2: C376.2 R64.1 U6.2(EN_LDO2)
FB_DCDC: C29.1 R83.1 R84.1 U6.9(FB_DCDC)
FB_LDO1: R68.1 R608.1 U6.11(FB_LDO1)
FB_LDO2: R44.1 R603.1 U6.14(FB_LDO2)
MIPI_RTCK: U132.16(B6) ; also on sheet 38
MIPI_TCK: U132.3(A1) U132.8(A6) ; also on sheet 38
MIPI_TDI: U132.4(A2) ; also on sheet 38
MIPI_TDO: U133.3(IA1) ; also on sheet 38
MIPI_TMS: U132.6(A4) ; also on sheet 38
MIPI_TRGRSTZ: R904.2 U132.9(A7) ; also on sheet 38
MIPI_TRST#: U132.5(A3) ; also on sheet 38
MODE: R75.2 R611.1 U6.7(MODE)
SEL_XDS: U37.15(~{E}) U41.22(~{OE}) U133.1(S) U134.1(S) ; also on sheet 38
SEL_XDS200_INV: U132.22(~{OE}) ; also on sheet 38
SOC_EMU00: U37.4(YA) ; also on sheet 38
SOC_EMU01: U37.7(YB) ; also on sheet 38
SOC_TCK: U134.4(YA) ; also on sheet 38
SOC_TDI: U134.7(YB) ; also on sheet 38
SOC_TDO: U59.3(A) ; also on sheet 38
SOC_TMS: U134.12(YD) ; also on sheet 38
SOC_TRST#: U134.9(YC) ; also on sheet 38
SPARE0: TP37.1(TP) U12.20(I/O_13)
SPARE1: TP38.1(TP) U12.19(I/O_12)
T_RTCK: R80.2 R783.2 U41.16(B6)
T_SRST_N: R122.2 R905.2 U41.9(A7)
T_TCK: R144.2 U41.3(A1) U41.8(A6)
T_TDI: R147.2 U41.4(A2)
T_TDIS: R72.1 R77.2 R889.2 TP36.1(TP)
T_TMS: R146.2 R643.2 U41.6(A4)
T_TRST_N: R145.2 U41.5(A3)
TPS65000_PG#: R67.1 TP29.1(TP) U4.2(A) U6.3(~{PG})
TRGRSTZ: U41.15(B7) U132.15(B7) ; also on sheet 11 45
uEMU0: R129.1 U12.33(I/O_23)
uEMU1: R125.1 U12.32(I/O_22)
uEXP0: R121.1 U12.29(I/O_19)
uEXP1: R114.1 U12.28(I/O_18)
uEXP2: R110.1 U12.27(I/O_17)
uEXP3: R104.1 U12.23(I/O_16)
uRTCK: R80.1 U12.22(I/O_15)
uSRSTn: R122.1 U12.31(I/O_21)
uTCK: R144.1 U12.34(I/O_24)
uTDI: R147.1 U12.38(I/O_27)
uTDIS: C386.1 R77.1 U12.18(I/O_11)
uTDO: R81.1 U12.21(I/O_14)
uTMS: R146.1 U12.37(I/O_26)
uTMSK: R643.1 U12.30(I/O_20)
uTRSTn: R145.1 U12.36(I/O_25)
XDS200_EMU0: R129.2 U37.2(IA0)
XDS200_EMU1: R125.2 U37.5(IB0)
XDS200_TDO: R81.2 U133.2(IA0)
XDS_SYS_RESETn: U2.1(~{RESE}T) ; also on sheet 41
N17118481: R108.2 R110.2 TP41.1(TP)
N17118483: R104.2 R115.2 TP39.1(TP)
N17118485: R95.2 R121.2 TP46.1(TP)
N17118487: R107.2 R114.2 TP44.1(TP)
N17138453: R113.1 U12.26(VCCIO2)
N17601404: D2.4(REF) R599.1 R600.2
N17601690: U2.3(~{MR}) U4.4(Y)
N17601710: C363.1 U2.4(CT)
N17628247: L2.1 U6.5(SW)
N18323233: R323.2 U41.21(B1)
N18323302: R353.1 U41.2(DIR)
N23802356: R864.2 U132.7(A5) U132.10(A8)
N23802386: R866.2 U132.21(B1)
N23802411: R865.1 U132.2(DIR)
N23881985: R697.1 U37.1(S)
N23882833: R868.1 U134.15(~{E})
N23883268: R869.2 U59.5(DIR)
N23883344: R867.1 U133.15(~{E})

Not connected (* = marked no-connect by the designer): D2 1(NC1)* 2(NC2)*; U4 1(NC)*; U37 3(IA1)* 6(IB1)* 9(YC)* 10(IC1)* 11(IC0)* 12(YD)* 13(ID1)* 14(ID0)*; U41 14(B8)* 17(B5)*; U132 14(B8)* 17(B5)*; U133 5(IB0)* 6(IB1)* 7(YB)* 9(YC)* 10(IC1)* 11(IC0)* 12(YD)* 13(ID1)* 14(ID0)*

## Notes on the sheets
sheet 43
- XDS200 CPLD
- JTAG HEADER FOR CPLD
- BUFFER XDS200
- BUFFER MIPI
sheet 44
- XDS200 POWER
- R1
- Optional - Advisory
  2.1.7, Set to operate as
  1.86V Zener.
- R2
- VO = 1.24*(1+R1/R2)
- 18.2K ~ 2.0V
- 22.1K ~ 1.91V
- 24.3K ~ 1.86V
- JTAG FET SWITCH
